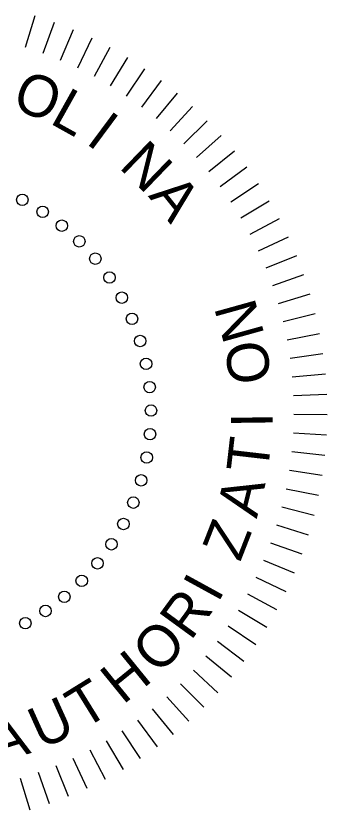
# Model space of a CAD drawing. Extents: x 1524103 to 2096450, y 1024229 to 1162569.
# Drawn here: x 2068303 to 2069480, y 1118904 to 1121911 of the extents above; entities that cross this region are included whole.
import ezdxf

# ---------------------------------------------------------------- set-up
doc = ezdxf.new("R2010")
doc.units = 0
doc.layers.add('RD_SHT_TX', color=7, linetype='Continuous')

msp = doc.modelspace()

# ---------------------------------------------------------------- linework, layer by layer
at = {"layer": 'RD_SHT_TX'}
for p, q in [((2068375, 1121911.2), (2068337.9, 1121791.4)), ((2068375, 1121911.2), (2068337.9, 1121791.4)), ((2068375, 1121911.2), (2068337.9, 1121791.4)), ((2068448, 1121886.5), (2068405.1, 1121768.6)), ((2068448, 1121886.5), (2068405.1, 1121768.6)), ((2068448, 1121886.5), (2068405.1, 1121768.6)), ((2068519.7, 1121858.3), (2068471.1, 1121742.6)), ((2068519.7, 1121858.3), (2068471.1, 1121742.6)), ((2068519.7, 1121858.3), (2068471.1, 1121742.6)), ((2068590, 1121826.5), (2068535.8, 1121713.4)), ((2068590, 1121826.5), (2068535.8, 1121713.4)), ((2068590, 1121826.5), (2068535.8, 1121713.4)), ((2068658.6, 1121791.4), (2068598.9, 1121681.1)), ((2068658.6, 1121791.4), (2068598.9, 1121681.1)), ((2068658.6, 1121791.4), (2068598.9, 1121681.1)), ((2068725.4, 1121753), (2068660.4, 1121645.7)), ((2068725.4, 1121753), (2068660.4, 1121645.7)), ((2068725.4, 1121753), (2068660.4, 1121645.7)), ((2068790.3, 1121711.3), (2068720.1, 1121607.4)), ((2068790.3, 1121711.3), (2068720.1, 1121607.4)), ((2068790.3, 1121711.3), (2068720.1, 1121607.4)), ((2068853, 1121666.5), (2068777.8, 1121566.1)), ((2068853, 1121666.5), (2068777.8, 1121566.1)), ((2068853, 1121666.5), (2068777.8, 1121566.1)), ((2068913.5, 1121618.6), (2068833.4, 1121522.1)), ((2068913.5, 1121618.6), (2068833.4, 1121522.1)), ((2068913.5, 1121618.6), (2068833.4, 1121522.1)), ((2068971.5, 1121567.9), (2068886.8, 1121475.4)), ((2068971.5, 1121567.9), (2068886.8, 1121475.4)), ((2068971.5, 1121567.9), (2068886.8, 1121475.4)), ((2069027, 1121514.4), (2068937.9, 1121426.1)), ((2069027, 1121514.4), (2068937.9, 1121426.1)), ((2069027, 1121514.4), (2068937.9, 1121426.1)), ((2069079.8, 1121458.2), (2068986.4, 1121374.4)), ((2069079.8, 1121458.2), (2068986.4, 1121374.4)), ((2069079.8, 1121458.2), (2068986.4, 1121374.4)), ((2069129.7, 1121399.5), (2069032.4, 1121320.4)), ((2069129.7, 1121399.5), (2069032.4, 1121320.4)), ((2069129.7, 1121399.5), (2069032.4, 1121320.4)), ((2069176.8, 1121338.5), (2069075.7, 1121264.2)), ((2069176.8, 1121338.5), (2069075.7, 1121264.2)), ((2069176.8, 1121338.5), (2069075.7, 1121264.2)), ((2069220.7, 1121275.2), (2069116.1, 1121206)), ((2069220.7, 1121275.2), (2069116.1, 1121206)), ((2069220.7, 1121275.2), (2069116.1, 1121206)), ((2069261.6, 1121209.8), (2069153.7, 1121145.8)), ((2069261.6, 1121209.8), (2069153.7, 1121145.8)), ((2069261.6, 1121209.8), (2069153.7, 1121145.8)), ((2069299.1, 1121142.5), (2069188.3, 1121083.8)), ((2069299.1, 1121142.5), (2069188.3, 1121083.8)), ((2069299.1, 1121142.5), (2069188.3, 1121083.8)), ((2069333.4, 1121073.4), (2069219.8, 1121020.3)), ((2069333.4, 1121073.4), (2069219.8, 1121020.3)), ((2069333.4, 1121073.4), (2069219.8, 1121020.3)), ((2069364.2, 1121002.7), (2069248.1, 1120955.3)), ((2069364.2, 1121002.7), (2069248.1, 1120955.3)), ((2069364.2, 1121002.7), (2069248.1, 1120955.3)), ((2069391.5, 1120930.6), (2069273.2, 1120888.9)), ((2069391.5, 1120930.6), (2069273.2, 1120888.9)), ((2069391.5, 1120930.6), (2069273.2, 1120888.9)), ((2069415.2, 1120857.3), (2069295, 1120821.4)), ((2069415.2, 1120857.3), (2069295, 1120821.4)), ((2069415.2, 1120857.3), (2069295, 1120821.4)), ((2069435.3, 1120782.9), (2069313.5, 1120752.9)), ((2069435.3, 1120782.9), (2069313.5, 1120752.9)), ((2069435.3, 1120782.9), (2069313.5, 1120752.9)), ((2069451.8, 1120707.6), (2069328.6, 1120683.6)), ((2069451.8, 1120707.6), (2069328.6, 1120683.6)), ((2069451.8, 1120707.6), (2069328.6, 1120683.6)), ((2069464.5, 1120631.5), (2069340.3, 1120613.7)), ((2069464.5, 1120631.5), (2069340.3, 1120613.7)), ((2069464.5, 1120631.5), (2069340.3, 1120613.7)), ((2069473.5, 1120555), (2069348.6, 1120543.2)), ((2069473.5, 1120555), (2069348.6, 1120543.2)), ((2069473.5, 1120555), (2069348.6, 1120543.2)), ((2069478.7, 1120478.1), (2069353.4, 1120472.4)), ((2069478.7, 1120478.1), (2069353.4, 1120472.4)), ((2069478.7, 1120478.1), (2069353.4, 1120472.4)), ((2069480.1, 1120401), (2069354.7, 1120401.5)), ((2069480.1, 1120401), (2069354.7, 1120401.5)), ((2069480.1, 1120401), (2069354.7, 1120401.5)), ((2069477.8, 1120323.9), (2069352.5, 1120330.6)), ((2069477.8, 1120323.9), (2069352.5, 1120330.6)), ((2069477.8, 1120323.9), (2069352.5, 1120330.6)), ((2069471.7, 1120247.1), (2069346.9, 1120259.9)), ((2069471.7, 1120247.1), (2069346.9, 1120259.9)), ((2069471.7, 1120247.1), (2069346.9, 1120259.9)), ((2069461.8, 1120170.7), (2069337.8, 1120189.6)), ((2069461.8, 1120170.7), (2069337.8, 1120189.6)), ((2069461.8, 1120170.7), (2069337.8, 1120189.6)), ((2069448.2, 1120094.8), (2069325.3, 1120119.7)), ((2069448.2, 1120094.8), (2069325.3, 1120119.7)), ((2069448.2, 1120094.8), (2069325.3, 1120119.7)), ((2069430.9, 1120019.7), (2069309.3, 1120050.6)), ((2069430.9, 1120019.7), (2069309.3, 1120050.6)), ((2069430.9, 1120019.7), (2069309.3, 1120050.6)), ((2069409.9, 1119945.5), (2069290, 1119982.4)), ((2069409.9, 1119945.5), (2069290, 1119982.4)), ((2069409.9, 1119945.5), (2069290, 1119982.4)), ((2069385.3, 1119872.4), (2069267.4, 1119915.1)), ((2069385.3, 1119872.4), (2069267.4, 1119915.1)), ((2069385.3, 1119872.4), (2069267.4, 1119915.1)), ((2069357.2, 1119800.7), (2069241.5, 1119849.1)), ((2069357.2, 1119800.7), (2069241.5, 1119849.1)), ((2069357.2, 1119800.7), (2069241.5, 1119849.1)), ((2069325.5, 1119730.4), (2069212.4, 1119784.4)), ((2069325.5, 1119730.4), (2069212.4, 1119784.4)), ((2069325.5, 1119730.4), (2069212.4, 1119784.4)), ((2069290.5, 1119661.7), (2069180.1, 1119721.2)), ((2069290.5, 1119661.7), (2069180.1, 1119721.2)), ((2069290.5, 1119661.7), (2069180.1, 1119721.2)), ((2069252.2, 1119594.8), (2069144.8, 1119659.7)), ((2069252.2, 1119594.8), (2069144.8, 1119659.7)), ((2069252.2, 1119594.8), (2069144.8, 1119659.7)), ((2069210.6, 1119529.9), (2069106.6, 1119600)), ((2069210.6, 1119529.9), (2069106.6, 1119600)), ((2069210.6, 1119529.9), (2069106.6, 1119600)), ((2069165.9, 1119467.1), (2069065.4, 1119542.2)), ((2069165.9, 1119467.1), (2069065.4, 1119542.2)), ((2069165.9, 1119467.1), (2069065.4, 1119542.2)), ((2069118.1, 1119406.6), (2069021.5, 1119486.5)), ((2069118.1, 1119406.6), (2069021.5, 1119486.5)), ((2069118.1, 1119406.6), (2069021.5, 1119486.5)), ((2069067.5, 1119348.5), (2068974.8, 1119433.1)), ((2069067.5, 1119348.5), (2068974.8, 1119433.1)), ((2069067.5, 1119348.5), (2068974.8, 1119433.1)), ((2069014, 1119293), (2068925.6, 1119382)), ((2069014, 1119293), (2068925.6, 1119382)), ((2069014, 1119293), (2068925.6, 1119382)), ((2068957.9, 1119240.1), (2068874, 1119333.3)), ((2068957.9, 1119240.1), (2068874, 1119333.3)), ((2068957.9, 1119240.1), (2068874, 1119333.3)), ((2068899.3, 1119190), (2068820.1, 1119287.3)), ((2068899.3, 1119190), (2068820.1, 1119287.3)), ((2068899.3, 1119190), (2068820.1, 1119287.3)), ((2068838.3, 1119142.9), (2068763.9, 1119243.9)), ((2068838.3, 1119142.9), (2068763.9, 1119243.9)), ((2068838.3, 1119142.9), (2068763.9, 1119243.9)), ((2068775, 1119098.8), (2068705.7, 1119203.4)), ((2068775, 1119098.8), (2068705.7, 1119203.4)), ((2068775, 1119098.8), (2068705.7, 1119203.4)), ((2068709.7, 1119057.9), (2068645.6, 1119165.7)), ((2068709.7, 1119057.9), (2068645.6, 1119165.7)), ((2068709.7, 1119057.9), (2068645.6, 1119165.7)), ((2068642.5, 1119020.3), (2068583.7, 1119131.1)), ((2068642.5, 1119020.3), (2068583.7, 1119131.1)), ((2068642.5, 1119020.3), (2068583.7, 1119131.1)), ((2068573.4, 1118985.9), (2068520.2, 1119099.5)), ((2068573.4, 1118985.9), (2068520.2, 1119099.5)), ((2068573.4, 1118985.9), (2068520.2, 1119099.5)), ((2068430.8, 1118927.6), (2068388.9, 1119045.9)), ((2068430.8, 1118927.6), (2068388.9, 1119045.9)), ((2068430.8, 1118927.6), (2068388.9, 1119045.9)), ((2068502.8, 1118955), (2068455.2, 1119071.1)), ((2068502.8, 1118955), (2068455.2, 1119071.1)), ((2068502.8, 1118955), (2068455.2, 1119071.1)), ((2068357.5, 1118903.8), (2068321.4, 1119023.9)), ((2068357.5, 1118903.8), (2068321.4, 1119023.9)), ((2068357.5, 1118903.8), (2068321.4, 1119023.9))]:
    msp.add_line(p, q, dxfattribs=at)
for centre in [(2068327.8, 1121214.7), (2068327.8, 1121214.7), (2068327.8, 1121214.7), (2068404.7, 1121169.4), (2068404.7, 1121169.4), (2068404.7, 1121169.4), (2068476.8, 1121116.8), (2068476.8, 1121116.8), (2068476.8, 1121116.8), (2068543.3, 1121057.4), (2068543.3, 1121057.4), (2068543.3, 1121057.4), (2068603.8, 1120991.8), (2068603.8, 1120991.8), (2068603.8, 1120991.8), (2068657.5, 1120920.5), (2068657.5, 1120920.5), (2068657.5, 1120920.5), (2068703.9, 1120844.3), (2068703.9, 1120844.3), (2068703.9, 1120844.3), (2068742.6, 1120764), (2068742.6, 1120764), (2068742.6, 1120764), (2068773.3, 1120680.2), (2068773.3, 1120680.2), (2068773.3, 1120680.2), (2068795.6, 1120593.8), (2068795.6, 1120593.8), (2068795.6, 1120593.8), (2068809.4, 1120505.6), (2068809.4, 1120505.6), (2068809.4, 1120505.6), (2068814.4, 1120416.6), (2068814.4, 1120416.6), (2068814.4, 1120416.6), (2068810.6, 1120327.4), (2068810.6, 1120327.4), (2068810.6, 1120327.4), (2068798.1, 1120239.1), (2068798.1, 1120239.1), (2068798.1, 1120239.1), (2068777, 1120152.4), (2068777, 1120152.4), (2068777, 1120152.4), (2068747.5, 1120068.2), (2068747.5, 1120068.2), (2068747.5, 1120068.2), (2068709.9, 1119987.3), (2068709.9, 1119987.3), (2068709.9, 1119987.3), (2068664.6, 1119910.4), (2068664.6, 1119910.4), (2068664.6, 1119910.4), (2068611.9, 1119838.4), (2068611.9, 1119838.4), (2068611.9, 1119838.4), (2068552.4, 1119771.9), (2068552.4, 1119771.9), (2068552.4, 1119771.9), (2068486.7, 1119711.6), (2068486.7, 1119711.6), (2068486.7, 1119711.6), (2068415.3, 1119658), (2068415.3, 1119658), (2068415.3, 1119658), (2068339.1, 1119611.7), (2068339.1, 1119611.7), (2068339.1, 1119611.7)]:
    msp.add_circle(centre, 21.7, dxfattribs=at)

# ---------------------------------------------------------------- texts
for s, rotation, p in [('O', 338.2003, (2068282.2, 1121564.9)), ('L', 330.8173, (2068427.3, 1121506.8)), ('I', 323.4344, (2068563.7, 1121430.6)), ('N', 316.0515, (2068689.2, 1121337.5)), ('A', 308.6686, (2068801.8, 1121229.1)), ('N', 105.5671, (2069244.1, 1120703.5)), ('O', 98.1841, (2069270.5, 1120529)), ('I', 90.8012, (2069274.3, 1120352.5)), ('T', 83.4183, (2069255.3, 1120177.1)), ('A', 76.0354, (2069214, 1120005.5)), ('Z', 68.6525, (2069151, 1119840.6)), ('I', 61.2696, (2069067.3, 1119685.2)), ('R', 53.8866, (2068964.4, 1119541.9)), ('O', 46.5037, (2068843.9, 1119412.9)), ('H', 39.1208, (2068707.8, 1119300.6)), ('T', 31.7379, (2068558.4, 1119206.6)), ('U', 24.355, (2068398.1, 1119132.6)), ('A', 16.972, (2068229.7, 1119079.8))]:
    msp.add_text(s, height=157.3, rotation=rotation, dxfattribs=at).set_placement(p)

doc.saveas('drawing.dxf')
